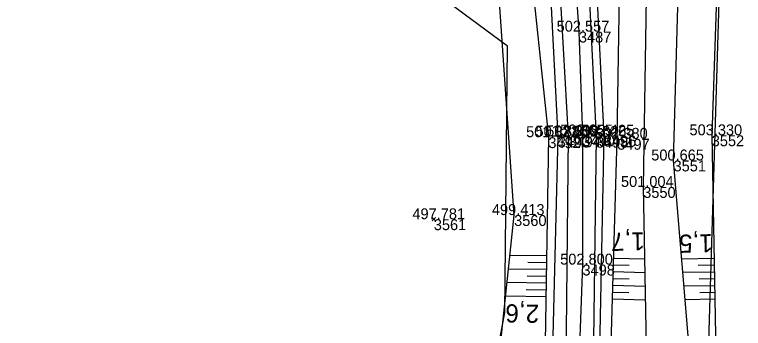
# Model space of a CAD drawing. Extents: x -1234191 to 23050, y -1290331 to -741191.
# Drawn here: x -864805.5 to -864725.2, y -1103717 to -1103682.5 of the extents above; entities that cross this region are included whole.
import ezdxf

# ---------------------------------------------------------------- set-up
doc = ezdxf.new("R2010")
doc.units = 0
for name, color, linetype in [('Vrstva 1', 7, 'Continuous'), ('Vrstva 4', 7, 'Continuous'), ('Vrstva 48', 7, 'Continuous'), ('Vrstva 49', 7, 'Continuous'), ('Vrstva 53', 7, 'Continuous'), ('Vrstva 55', 7, 'Continuous'), ('Vrstva 60', 7, 'Continuous'), ('Vrstva 61', 7, 'Continuous')]:
    doc.layers.add(name, color=color, linetype=linetype)

msp = doc.modelspace()

# ---------------------------------------------------------------- linework, layer by layer
at = {"layer": 'Vrstva 1'}
msp.add_lwpolyline([(-864793.889, -1103512.114), (-864783.846, -1103532.561), (-864777.779, -1103545.505), (-864772.313, -1103557.879), (-864767.014, -1103571.07), (-864765.039, -1103576.441), (-864763.844, -1103579.817), (-864763.627, -1103580.437), (-864761.439, -1103586.873), (-864759.929, -1103591.526), (-864756.554, -1103602.699), (-864754.035, -1103612.065), (-864749.646, -1103631.615), (-864746.393, -1103651.415), (-864744.316, -1103670.035), (-864743.32, -1103684.375), (-864742.928, -1103695.791), (-864742.93, -1103709.996), (-864743.322, -1103720.931)], dxfattribs=at)
at = {"layer": 'Vrstva 4'}
for points in [[(-864760.304, -1103585.507), (-864758.01, -1103589.284), (-864751.444, -1103611.627), (-864747.016, -1103630.542), (-864743.725, -1103651.465), (-864741.864, -1103669.866), (-864740.574, -1103695.824), (-864741.07, -1103721.125), (-864742.528, -1103740.954), (-864744.989, -1103760.616), (-864748.394, -1103780.311), (-864753.72, -1103800.993), (-864758.708, -1103817.793), (-864762.508, -1103827.219), (-864764.879, -1103833.984), (-864767.284, -1103841.096), (-864775.975, -1103861.988)], [(-864760.304, -1103585.507), (-864752.461, -1103611.71), (-864748.067, -1103631.259), (-864744.68, -1103651.488), (-864742.713, -1103669.874), (-864741.435, -1103695.94), (-864741.734, -1103721.107), (-864743.546, -1103740.884), (-864745.934, -1103760.969), (-864749.64, -1103780.578), (-864754.484, -1103800.203), (-864759.894, -1103817.389), (-864768.323, -1103840.531)], [(-864763.19, -1103586.386), (-864762.719, -1103590.246), (-864756.267, -1103612.613), (-864751.922, -1103631.922), (-864748.919, -1103652.31), (-864746.969, -1103670.202), (-864745.646, -1103695.918), (-864746.276, -1103720.801), (-864747.842, -1103740.601), (-864750.431, -1103760.522), (-864754.066, -1103779.853), (-864758.55, -1103798.895), (-864764.264, -1103818.201), (-864765.856, -1103824.388)], [(-864779.457, -1103860.305), (-864770.917, -1103839.588), (-864762.979, -1103818.527), (-864757.032, -1103799.344), (-864752.45, -1103780.065), (-864748.927, -1103760.644), (-864746.257, -1103740.695), (-864744.716, -1103720.855), (-864744.47, -1103695.892), (-864745.952, -1103670.077)]]:
    msp.add_lwpolyline(points, dxfattribs=at)
at = {"layer": 'Vrstva 48'}
for p, q in [((-864746.881, -1103709.045), (-864750.92, -1103708.983)), ((-864739.481, -1103709.273), (-864736.089, -1103709.374)), ((-864728.422, -1103709.313), (-864731.982, -1103709.382)), ((-864746.893, -1103709.795), (-864748.946, -1103709.763)), ((-864739.503, -1103710.022), (-864737.789, -1103710.073)), ((-864728.408, -1103710.063), (-864730.163, -1103710.097)), ((-864746.904, -1103710.545), (-864751.077, -1103710.481)), ((-864739.525, -1103710.772), (-864736.062, -1103710.875)), ((-864728.393, -1103710.813), (-864731.856, -1103710.88)), ((-864746.915, -1103711.294), (-864749.036, -1103711.262)), ((-864739.548, -1103711.522), (-864737.798, -1103711.574)), ((-864728.379, -1103711.563), (-864730.086, -1103711.596)), ((-864746.927, -1103712.044), (-864751.235, -1103711.979)), ((-864739.57, -1103712.271), (-864736.034, -1103712.376)), ((-864728.364, -1103712.312), (-864731.73, -1103712.377)), ((-864746.938, -1103712.794), (-864749.126, -1103712.761)), ((-864739.592, -1103713.021), (-864737.806, -1103713.074)), ((-864728.35, -1103713.062), (-864730.009, -1103713.094)), ((-864746.95, -1103713.544), (-864751.392, -1103713.477)), ((-864739.614, -1103713.771), (-864736.007, -1103713.878)), ((-864728.335, -1103713.812), (-864731.605, -1103713.875))]:
    msp.add_line(p, q, dxfattribs=at)
at = {"layer": 'Vrstva 49'}
for p, q in [((-864759.128, -1103704.83), (-864759.482, -1103705.184)), ((-864759.482, -1103704.83), (-864759.128, -1103705.184))]:
    msp.add_line(p, q, dxfattribs=at)
for points in [[(-864744.155, -1103761.31), (-864741.527, -1103741.195), (-864739.836, -1103721.226), (-864739.091, -1103696.162), (-864738.846, -1103680.2), (-864735.957, -1103677.345), (-864734.831, -1103672.686), (-864741.504, -1103665.701), (-864742.759, -1103651.286)], [(-864748.952, -1103665.207), (-864748.677, -1103669.978), (-864748.92, -1103674.757), (-864746.682, -1103695.987), (-864747.06, -1103720.781)], [(-864750.454, -1103704.546), (-864752.393, -1103676.291), (-864750.902, -1103668.502)], [(-864727.946, -1103673.994), (-864728.683, -1103695.777), (-864728.144, -1103723.734), (-864728.766, -1103743.695)], [(-864732.454, -1103674.144), (-864735.903, -1103680.631), (-864736.233, -1103701.459), (-864735.879, -1103720.9)], [(-864732.893, -1103698.545), (-864732.399, -1103680.288), (-864732.454, -1103674.144)], [(-864730.022, -1103754.148), (-864730.863, -1103742.731), (-864731.012, -1103720.925), (-864732.893, -1103698.545)], [(-864757.301, -1103757.029), (-864754.537, -1103737.797), (-864751.952, -1103718.809), (-864750.454, -1103704.546)]]:
    msp.add_lwpolyline(points, dxfattribs=at)
at = {"layer": 'Vrstva 53'}
for points in [[(-864851.8, -1103965.2), (-864832.93, -1103934.25), (-864802.44, -1103886.38), (-864769.72, -1103812.69), (-864751.48, -1103715.25), (-864751.19, -1103685.96), (-864767.18, -1103674.13), (-864782.08, -1103622.93), (-864787.15, -1103586.96), (-864794.59, -1103552.36), (-864798.3, -1103518.33), (-864820.12, -1103492.38), (-864862.25, -1103399.25), (-864883.05, -1103347.48), (-864889.03, -1103323.28), (-864892.77, -1103263.78)], [(-864869.74, -1103303.4), (-864855.1, -1103331.53), (-864834.52, -1103376.94), (-864795.6, -1103454.6), (-864803.1, -1103460.5), (-864775.38, -1103525.99), (-864764.18, -1103538.93), (-864727.24, -1103659.36), (-864730.26, -1103758.23), (-864750.67, -1103831.76), (-864786.8, -1103900.96), (-864807.11, -1103958.19)]]:
    msp.add_lwpolyline(points, dxfattribs=at)
at = {"layer": 'Vrstva 55'}
msp.add_lwpolyline([(-864869.74, -1103303.4), (-864855.1, -1103331.53), (-864834.52, -1103376.94), (-864795.6, -1103454.6), (-864803.1, -1103460.5), (-864775.38, -1103525.99), (-864764.18, -1103538.93), (-864727.24, -1103659.36), (-864730.26, -1103758.23), (-864750.67, -1103831.76), (-864786.8, -1103900.96), (-864807.11, -1103958.19)], dxfattribs=at)
at = {"layer": 'Vrstva 60'}
for p, q in [((-864743.32, -1103684.375), (-864743.32, -1103684.375)), ((-864746.682, -1103695.987), (-864746.682, -1103695.987)), ((-864745.646, -1103695.918), (-864745.646, -1103695.918)), ((-864744.47, -1103695.892), (-864744.47, -1103695.892)), ((-864742.928, -1103695.791), (-864742.928, -1103695.791)), ((-864741.435, -1103695.94), (-864741.435, -1103695.94)), ((-864740.574, -1103695.824), (-864740.574, -1103695.824)), ((-864739.091, -1103696.162), (-864739.091, -1103696.162)), ((-864728.683, -1103695.777), (-864728.683, -1103695.777)), ((-864732.893, -1103698.545), (-864732.893, -1103698.545)), ((-864736.233, -1103701.459), (-864736.233, -1103701.459)), ((-864750.454, -1103704.546), (-864750.454, -1103704.546)), ((-864759.305, -1103705.007), (-864759.305, -1103705.007)), ((-864742.93, -1103709.996), (-864742.93, -1103709.996))]:
    msp.add_line(p, q, dxfattribs=at)

# ---------------------------------------------------------------- texts
at = {"layer": 'Vrstva 48'}
for s, rotation, p in [('1,7', 181.04318, (-864736.075, -1103706.428)), ('1,5', 181.1045, (-864728.591, -1103706.638)), ('2,6', 179.12656, (-864747.685, -1103714.409))]:
    msp.add_text(s, height=2, rotation=rotation, dxfattribs=at).set_placement(p)
at = {"layer": 'Vrstva 60'}
for s, p in [('3487', (-864743.32, -1103685.575)), ('3492', (-864746.682, -1103697.187)), ('3493', (-864745.646, -1103697.118)), ('3494', (-864744.47, -1103697.092)), ('3490', (-864742.928, -1103696.991)), ('3495', (-864741.435, -1103697.14)), ('3496', (-864740.574, -1103697.024)), ('3497', (-864739.091, -1103697.362)), ('3552', (-864728.683, -1103696.977)), ('3551', (-864732.893, -1103699.745)), ('3550', (-864736.233, -1103702.659)), ('3560', (-864750.454, -1103705.746)), ('3561', (-864759.305, -1103706.207)), ('3498', (-864742.93, -1103711.196))]:
    msp.add_text(s, height=1.2, dxfattribs=at).set_placement(p)
at = {"layer": 'Vrstva 61'}
for s, p in [('502.557', (-864745.772, -1103684.375)), ('501.823', (-864749.134, -1103695.987)), ('501.888', (-864748.1, -1103695.918)), ('502.339', (-864746.924, -1103695.892)), ('502.655', (-864745.384, -1103695.791)), ('502.626', (-864743.887, -1103695.94)), ('502.425', (-864743.03, -1103695.824)), ('502.380', (-864741.542, -1103696.162)), ('503.330', (-864731.134, -1103695.777)), ('500.665', (-864735.349, -1103698.545)), ('501.004', (-864738.684, -1103701.459)), ('499.413', (-864752.906, -1103704.546)), ('497.781', (-864761.662, -1103705.007)), ('502.800', (-864745.381, -1103709.996))]:
    msp.add_text(s, height=1.2, dxfattribs=at).set_placement(p)

doc.saveas('drawing.dxf')
